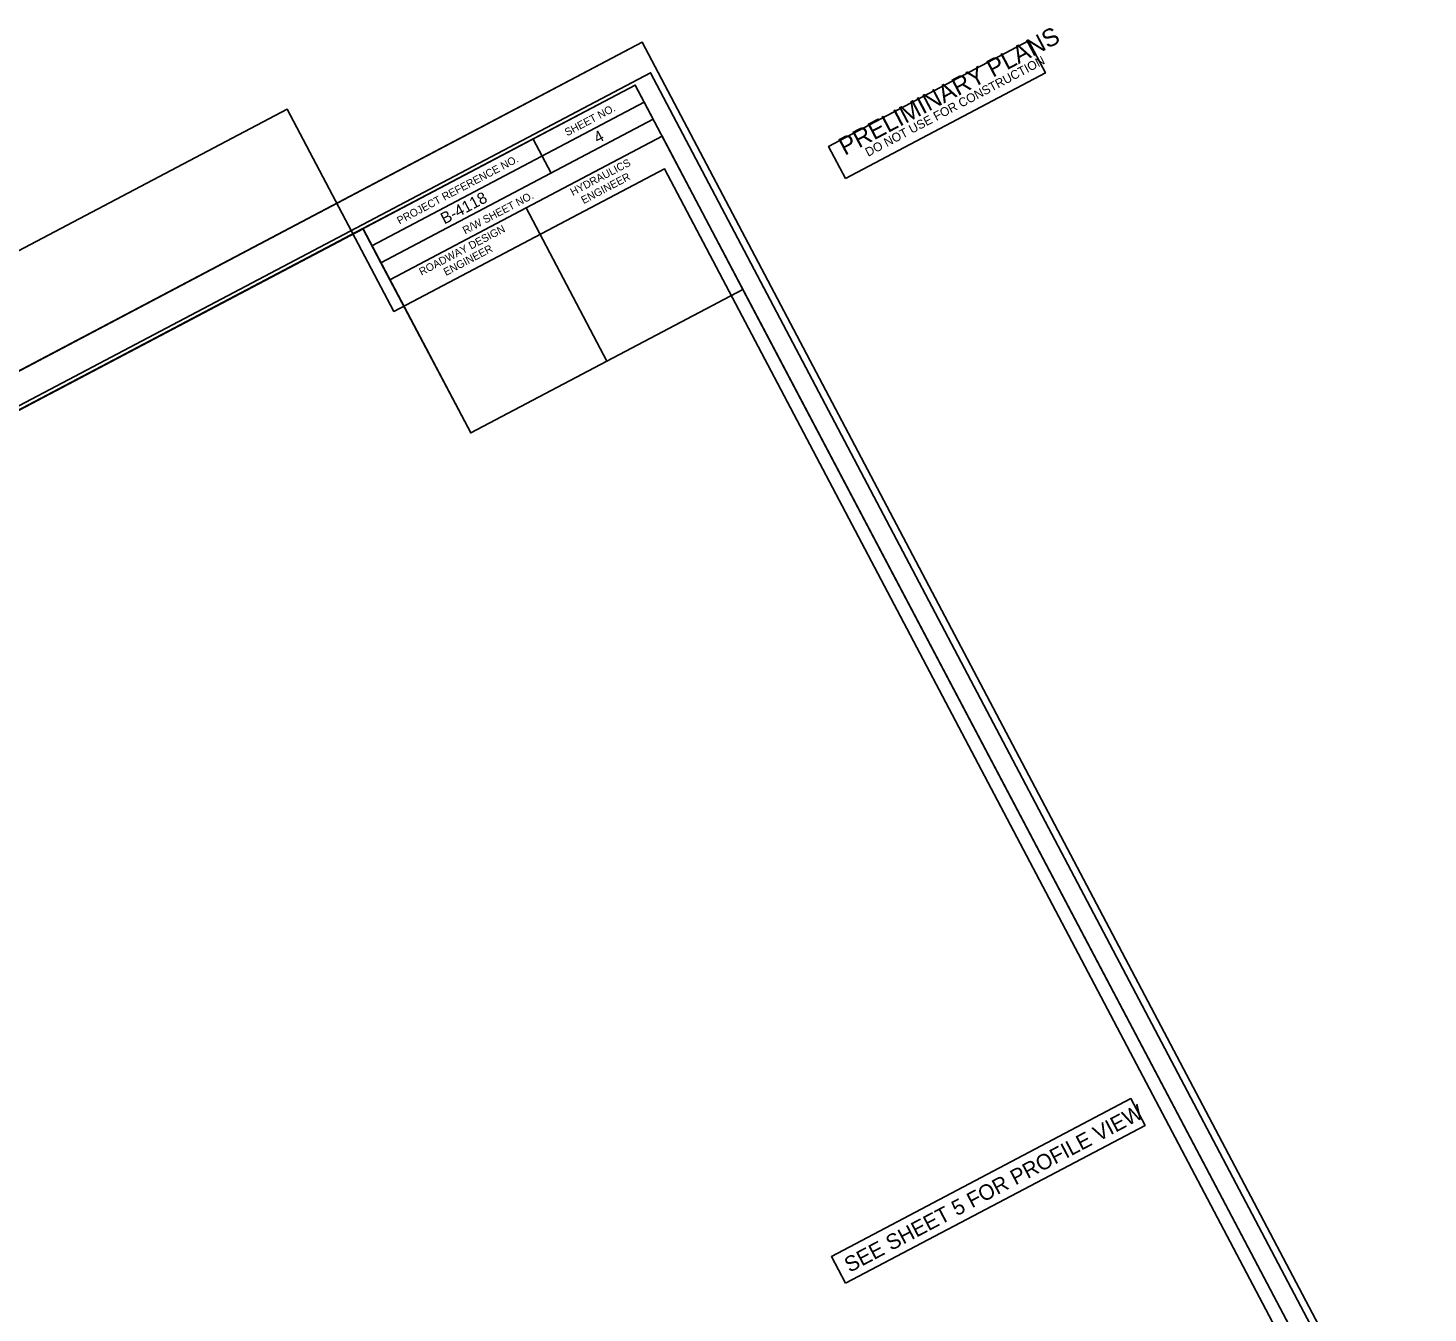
# Model space of a CAD drawing. Extents: x 1380651 to 1383136, y 594581 to 596344.
# Drawn here: x 1381741 to 1382651, y 595509 to 596344 of the extents above; entities that cross this region are included whole.
import ezdxf

# ---------------------------------------------------------------- set-up
doc = ezdxf.new("R2010")
doc.units = 0
for name, color, linetype in [('Prop DSN Text', 7, 'Continuous'), ('Prop Grid Mask', 7, 'Continuous'), ('Sheet Clip Boundary CELL', 7, 'Continuous'), ('Sheet Cutting Line CELL', 7, 'Continuous'), ('Sheet Data Field CELL', 7, 'Continuous'), ('Sheet Layout Plan Border', 7, 'Continuous'), ('Sheet Plan CELL', 7, 'Continuous'), ('Sheet Plot Border Inside CELL', 7, 'Continuous'), ('Sheet Plot Border Outside CELL', 7, 'Continuous'), ('Sheet Sticker Preliminary CELL', 7, 'Continuous')]:
    doc.layers.add(name, color=color, linetype=linetype)

msp = doc.modelspace()

# ---------------------------------------------------------------- linework, layer by layer
at = {"layer": 'Prop Grid Mask'}
msp.add_lwpolyline([(1382272.07, 595528.66), (1382466.78, 595631.31), (1382457.61, 595648.69), (1382262.91, 595546.05)], close=True, dxfattribs=at)
at = {"layer": 'Sheet Clip Boundary CELL'}
msp.add_lwpolyline([(1381254.23, 594780.01), (1382566.26, 595471.7), (1382154.39, 596252.97), (1381978.55, 596160.27), (1381909.21, 596291.79), (1380773.01, 595692.8)], close=True, dxfattribs=at)
at = {"layer": 'Sheet Cutting Line CELL'}
msp.add_line((1382140.02, 596335.19), (1380650.8, 595550.09), dxfattribs=at)
at = {"layer": 'Sheet Layout Plan Border'}
msp.add_lwpolyline([(1381298.21, 594679), (1382625.14, 595378.54), (1382205.45, 596174.64), (1382028.49, 596081.35), (1381958.53, 596214.06), (1380808.55, 595607.8)], close=True, dxfattribs=at)
at = {"layer": 'Sheet Plan CELL'}
for p, q in [((1381964.34, 596202.98), (1382141.31, 596296.26)), ((1381970.2, 596191.9), (1382147.14, 596285.21)), ((1381970.2, 596191.9), (1382147.14, 596285.21)), ((1382069.12, 596272.32), (1382080.82, 596250.23)), ((1382064.53, 596227.51), (1382116.99, 596128.03)), ((1381970.2, 596191.9), (1381976.02, 596180.85))]:
    msp.add_line(p, q, dxfattribs=at)
for points in [[(1382135.49, 596307.38), (1380808.56, 595607.84), (1381298.23, 594679.01), (1382625.14, 595378.54)], [(1381958.5, 596214.09), (1382135.49, 596307.38), (1382147.14, 596285.21), (1381970.2, 596191.9)], [(1382064.53, 596227.51), (1382152.97, 596274.15), (1382205.45, 596174.63), (1382117, 596127.98)], [(1381976.02, 596180.85), (1382064.53, 596227.51), (1382117, 596127.98), (1382028.49, 596081.35)], [(1381298.23, 594679.01), (1380808.55, 595607.8), (1381958.5, 596214.09), (1382028.49, 596081.35), (1382205.45, 596174.63), (1382625.14, 595378.54)]]:
    msp.add_lwpolyline(points, close=True, dxfattribs=at)
at = {"layer": 'Sheet Plot Border Inside CELL'}
msp.add_lwpolyline([(1381163.62, 594605.21), (1382637.35, 595382.15), (1382145.37, 596315.4), (1380671.62, 595538.46)], close=True, dxfattribs=at)
at = {"layer": 'Sheet Plot Border Outside CELL'}
msp.add_lwpolyline([(1381161.45, 594581.45), (1382650.68, 595366.55), (1382140.02, 596335.19), (1380650.8, 595550.09)], close=True, dxfattribs=at)
at = {"layer": 'Sheet Sticker Preliminary CELL'}
msp.add_lwpolyline([(1382272.01, 596246.74), (1382261.05, 596267.53), (1382391.09, 596336.08), (1382402.05, 596315.29)], close=True, dxfattribs=at)

# ---------------------------------------------------------------- texts
at = {"layer": 'Prop DSN Text'}
msp.add_text('SEE SHEET 5 FOR PROFILE VIEW', height=10, rotation=27.7977, dxfattribs=at).set_placement((1382274.73, 595535.4))
at = {"layer": 'Sheet Data Field CELL'}
for s, p in [('4', (1382110.95, 596269.29)), ('B-4118', (1382011.43, 596216.75))]:
    msp.add_text(s, height=7.5, rotation=27.7977, dxfattribs=at).set_placement(p)
at = {"layer": 'Sheet Plan CELL'}
for s, height, p in [('SHEET NO.', 5, (1382091.21, 596274.06)), ('PROJECT REFERENCE NO.', 5.0001, (1381982.21, 596216.72)), ('HYDRAULICS', 5, (1382094.87, 596235.28)), ('ENGINEER', 5, (1382101.91, 596229.99)), ('R/W SHEET NO.', 5.0001, (1382024.91, 596210.35)), ('ROADWAY DESIGN', 5.0001, (1381996.57, 596183.43)), ('ENGINEER', 5, (1382012.45, 596183.28))]:
    msp.add_text(s, height=height, rotation=27.7977, dxfattribs=at).set_placement(p)
at = {"layer": 'Sheet Sticker Preliminary CELL'}
for s, height, p in [('PRELIMINARY PLANS', 11.52, (1382271.63, 596261.4)), ('DO NOT USE FOR CONSTRUCTION', 5.76, (1382286.81, 596260.7))]:
    msp.add_text(s, height=height, rotation=27.7977, dxfattribs=at).set_placement(p)

doc.saveas('drawing.dxf')
